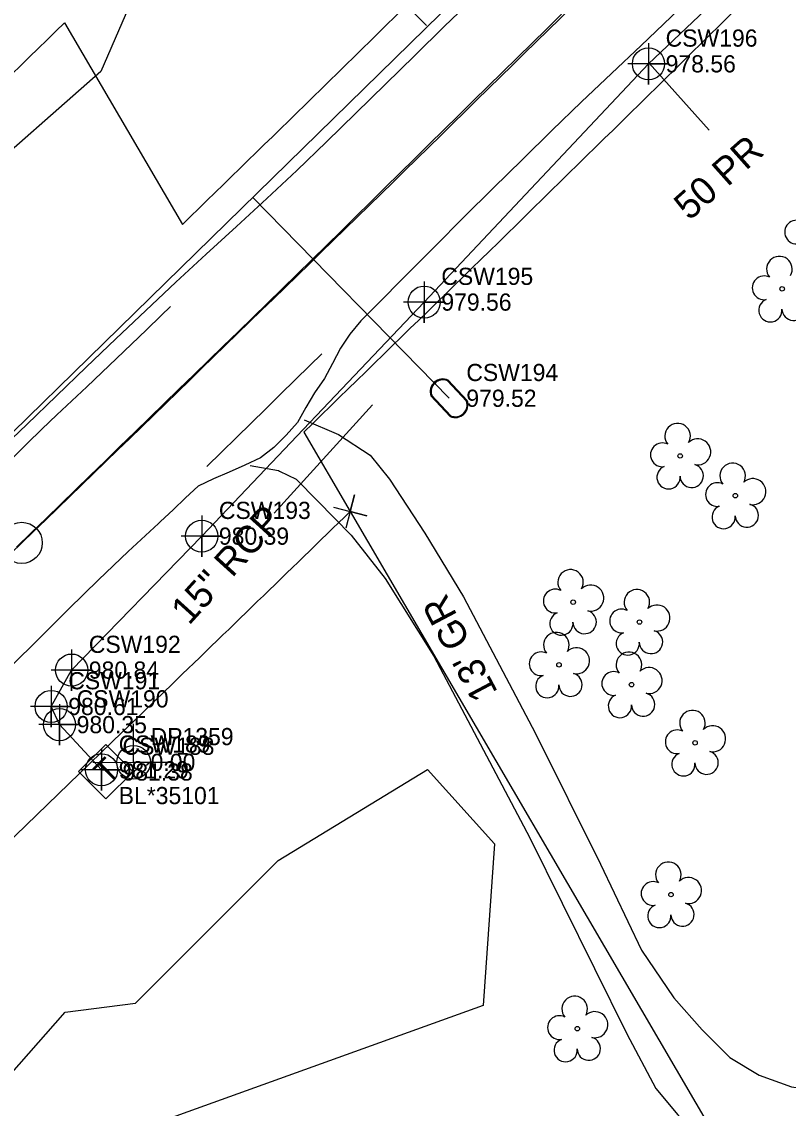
# Model space of a CAD drawing. Extents: x 1182322 to 1186765, y 572295 to 575411.
# Drawn here: x 1185163.2 to 1185274.8, y 574684.8 to 574843 of the extents above; entities that cross this region are included whole.
import ezdxf

# ---------------------------------------------------------------- set-up
doc = ezdxf.new("R2010")
doc.units = 0
for name, color, linetype in [('COGO Default Chain', 7, 'Continuous'), ('Exist Horizontal Alignment', 7, 'Continuous'), ('Exist Horizontal Alignment Point', 7, 'Continuous'), ('Exist Property Corner CELL', 7, 'Continuous'), ('Exist Property Line', 7, 'Continuous'), ('Exist Right of Way Line', 7, 'Continuous'), ('Exist Roads EOP', 7, 'Continuous'), ('Exist Roads EOT', 7, 'Continuous'), ('Exist Roads Soil', 7, 'Continuous'), ('Exist Roads Soil Text', 7, 'Continuous'), ('Exist Structure Minor Pipes RCP 15 Inch', 7, 'Continuous'), ('Exist Structure Minor Pipes RCP 15 Inch Text', 7, 'Continuous'), ('Exist Utilities Power Joint Use Telephone CELL', 7, 'Continuous'), ('Exist Utilities Power Joint Use Telephone Cogo Elevation', 7, 'Continuous'), ('Exist Utilities Power Joint Use Telephone Cogo Number', 7, 'Continuous'), ('Exist Utilities Telephone Pedestal CELL', 7, 'Continuous'), ('Exist Utilities Telephone Pedestal Cogo Elevation', 7, 'Continuous'), ('Exist Utilities Telephone Pedestal Cogo Number', 7, 'Continuous'), ('Exist Utilities Telephone UG Cable SUE LOS C', 7, 'Continuous'), ('Exist Utilities Telephone UG Cable SUE LOS C Cogo Comment', 7, 'Continuous'), ('Exist Utilities Telephone UG Cable SUE LOS C Cogo Elevation', 7, 'Continuous'), ('Exist Utilities Telephone UG Cable SUE LOS C Cogo Number', 7, 'Continuous'), ('Exist Utilities Telephone UG Cable SUE LOS C Cogo Point CELL', 7, 'Continuous'), ('Exist Utilities Telephone UG Cable SUE LOS C Leader', 7, 'Continuous'), ('Exist Utilities Telephone UG Cable SUE LOS C Text', 7, 'Continuous'), ('Exist Utilities Water Meter CELL', 7, 'Continuous'), ('Exist Utilities Water Meter Cogo Elevation', 7, 'Continuous'), ('Exist Utilities Water Meter Cogo Number', 7, 'Continuous'), ('Exist Utilities Water UG Line SUE LOS C', 7, 'Continuous'), ('Exist Vegetation Tree CELL', 7, 'Continuous'), ('Exist Vegetation Woods Line', 7, 'Continuous')]:
    doc.layers.add(name, color=color, linetype=linetype)

msp = doc.modelspace()

# ---------------------------------------------------------------- linework, layer by layer
at = {"layer": 'COGO Default Chain'}
msp.add_arc((1175733.04, 584524.62), 13569.69, 314.022628, 314.679808, dxfattribs=at)
at = {"layer": 'Exist Horizontal Alignment'}
for centre, radius, start, end in [((1175733.04, 584524.62), 13569.69, 314.022628, 314.679808), ((1211496.85, 547519.36), 37893.3, 134.022628, 134.231777)]:
    msp.add_arc(centre, radius, start, end, dxfattribs=at)
at = {"layer": 'Exist Horizontal Alignment Point'}
msp.add_circle((1185163.19, 574767.13), 3, dxfattribs=at)
at = {"layer": 'Exist Property Corner CELL'}
msp.add_line((1185211.02, 574771.7), (1185211.02, 574771.7), dxfattribs=at)
msp.add_lwpolyline([(1185208.6, 574772.34), (1185213.44, 574771.07), (1185211.02, 574771.7), (1185211.66, 574774.12), (1185210.39, 574769.29)], dxfattribs=at)
at = {"layer": 'Exist Property Line'}
msp.add_line((1185211.02, 574771.7), (1185330.03, 574568.05), dxfattribs=at)
at = {"layer": 'Exist Right of Way Line'}
for p, q in [((1185169.44, 574842.87), (1185186.59, 574813.51)), ((1185204.26, 574783.27), (1185211.02, 574771.7))]:
    msp.add_line(p, q, dxfattribs=at)
for centre, radius, start, end in [((1175733.04, 584524.62), 13552.69, 314.230039, 314.679808), ((1175733.04, 584524.62), 13586.69, 314.194478, 314.679808), ((1175733.04, 584524.62), 13519.69, 314.022628, 314.264731), ((1175733.04, 584524.62), 13599.69, 314.022628, 314.18093), ((1211496.85, 547519.36), 37863.3, 134.022628, 134.231777)]:
    msp.add_arc(centre, radius, start, end, dxfattribs=at)
at = {"layer": 'Exist Roads EOP'}
for points in [[(1185279.2, 574864.7), (1185274.93, 574860.49), (1185270.66, 574856.28), (1185266.37, 574852.09), (1185262.07, 574847.9), (1185257.74, 574843.74), (1185253.37, 574839.57), (1185249.07, 574835.46), (1185244.71, 574831.33), (1185240.4, 574827.17), (1185236.11, 574822.97), (1185231.83, 574818.77), (1185227.59, 574814.53), (1185223.35, 574810.28), (1185223.17, 574810.11)], [(1185159.58, 574780.24), (1185163.94, 574784.36), (1185168.25, 574788.54), (1185172.56, 574792.71), (1185176.91, 574796.84), (1185181.28, 574800.95), (1185185.64, 574805.07), (1185190.03, 574809.16), (1185194.46, 574813.2), (1185198.88, 574817.26), (1185203.26, 574821.35), (1185207.59, 574825.51), (1185211.86, 574829.72), (1185216.15, 574833.91), (1185220.43, 574838.11), (1185224.72, 574842.31), (1185229, 574846.51)], [(1185223.16, 574810.1), (1185221.39, 574808.33), (1185219.63, 574806.56), (1185217.86, 574804.79), (1185216.1, 574803.01), (1185214.34, 574801.24), (1185212.59, 574799.46), (1185210.98, 574797.54), (1185209.6, 574795.46), (1185208.44, 574793.24), (1185207.26, 574791.04), (1185205.82, 574789), (1185204.58, 574786.83), (1185203.36, 574784.65), (1185201.69, 574782.79), (1185199.92, 574781.02), (1185197.94, 574779.51), (1185195.67, 574778.46), (1185193.41, 574777.41), (1185191.1, 574776.47), (1185188.86, 574775.38), (1185187.04, 574773.67), (1185185.22, 574771.96), (1185183.39, 574770.25), (1185183.1, 574769.97)], [(1185183.09, 574769.97), (1185178.71, 574765.86), (1185174.37, 574761.73), (1185170.07, 574757.54), (1185165.82, 574753.31), (1185161.56, 574749.08), (1185157.3, 574744.86), (1185153.04, 574740.64), (1185148.78, 574736.42), (1185144.49, 574732.22), (1185140.14, 574728.09), (1185135.79, 574723.96), (1185131.52, 574719.75), (1185127.31, 574715.47), (1185123.09, 574711.21), (1185118.73, 574707.09), (1185114.39, 574702.94), (1185110.1, 574698.74), (1185105.81, 574694.56), (1185101.51, 574690.37), (1185097.22, 574686.18), (1185092.92, 574682)]]:
    msp.add_lwpolyline(points, dxfattribs=at)
at = {"layer": 'Exist Roads EOT'}
for points in [[(1185241.78, 574844.09), (1185239.64, 574841.99), (1185237.5, 574839.89), (1185235.36, 574837.78), (1185233.22, 574835.68), (1185231.08, 574833.58), (1185228.94, 574831.47), (1185226.81, 574829.37), (1185224.67, 574827.26), (1185222.53, 574825.16), (1185220.39, 574823.06), (1185218.26, 574820.95), (1185216.12, 574818.85), (1185213.98, 574816.74), (1185211.85, 574814.64), (1185209.71, 574812.53), (1185207.57, 574810.43), (1185205.43, 574808.33), (1185203.28, 574806.24), (1185201.13, 574804.14), (1185198.98, 574802.05), (1185196.84, 574799.96), (1185194.69, 574797.87), (1185192.54, 574795.77), (1185190.39, 574793.68), (1185188.24, 574791.59), (1185186.09, 574789.5), (1185183.94, 574787.41), (1185181.79, 574785.32), (1185179.64, 574783.23), (1185177.48, 574781.14), (1185175.33, 574779.05), (1185173.18, 574776.96), (1185171.03, 574774.87), (1185168.88, 574772.78), (1185166.73, 574770.69), (1185164.58, 574768.59), (1185162.43, 574766.5)], [(1185161.83, 574779.48), (1185163.97, 574781.58), (1185166.11, 574783.68), (1185168.29, 574785.75), (1185170.47, 574787.8), (1185172.66, 574789.86), (1185174.84, 574791.92), (1185177.01, 574793.99), (1185179.17, 574796.06), (1185181.34, 574798.14), (1185183.48, 574800.24), (1185184.83, 574801.56)], [(1185190.16, 574778.26), (1185192.3, 574780.36), (1185194.44, 574782.46), (1185196.58, 574784.56), (1185198.72, 574786.67), (1185200.86, 574788.77), (1185203, 574790.87), (1185205.15, 574792.96), (1185206.88, 574794.64)]]:
    msp.add_lwpolyline(points, dxfattribs=at)
at = {"layer": 'Exist Roads Soil'}
for points in [[(1185204.3, 574785.05), (1185209.31, 574782.91), (1185213.93, 574779.91), (1185216.72, 574776.43), (1185221.87, 574768.53), (1185227.5, 574759.27), (1185238.01, 574739.38), (1185247.45, 574720.37), (1185253.42, 574707.82), (1185258.15, 574700.91), (1185262.25, 574696.25), (1185266.32, 574692.19)], [(1185196.45, 574778.4), (1185200.57, 574777.69), (1185200.72, 574777.58), (1185203.14, 574776.4), (1185203.14, 574776.4), (1185206.28, 574773.23), (1185206.28, 574773.23), (1185211.16, 574768.24), (1185211.16, 574768.24), (1185216.11, 574761.96), (1185216.11, 574761.96), (1185223.19, 574750.64), (1185237.19, 574724.16), (1185251.32, 574695.67), (1185255.5, 574687.68)], [(1185266.32, 574692.19), (1185270.59, 574689.62), (1185275.28, 574687.95), (1185280.22, 574687.22), (1185285.21, 574687.48), (1185290.06, 574688.71)], [(1185255.5, 574687.68), (1185258.71, 574683.86), (1185262.44, 574680.55), (1185266.62, 574677.81), (1185271.15, 574675.71), (1185275.93, 574674.3), (1185280.88, 574673.59), (1185285.87, 574673.61), (1185290.81, 574674.36), (1185295.59, 574675.81)]]:
    msp.add_lwpolyline(points, dxfattribs=at)
at = {"layer": 'Exist Structure Minor Pipes RCP 15 Inch'}
msp.add_line((1185199.94, 574771.48), (1185214.25, 574787.25), dxfattribs=at)
at = {"layer": 'Exist Utilities Power Joint Use Telephone CELL'}
msp.add_line((1185179.46, 574735.18), (1185179.46, 574735.18), dxfattribs=at)
msp.add_lwpolyline([(1185173.53, 574735.18), (1185184.86, 574735.14), (1185179.46, 574735.16), (1185179.46, 574740.8)], dxfattribs=at)
msp.add_circle((1185179.47, 574735.19), 2.45, dxfattribs=at)
at = {"layer": 'Exist Utilities Telephone Pedestal CELL'}
msp.add_line((1185175.37, 574733.77), (1185175.37, 574733.77), dxfattribs=at)
msp.add_lwpolyline([(1185175.42, 574729.85), (1185179.4, 574733.78), (1185175.46, 574737.76), (1185171.48, 574733.83), (1185175.42, 574729.85)], dxfattribs=at)
at = {"layer": 'Exist Utilities Telephone UG Cable SUE LOS C'}
msp.add_lwpolyline([(1185174.81, 574734.09), (1185168.69, 574740.67), (1185167.47, 574743.31), (1185170.46, 574748.61), (1185189.4, 574768.11), (1185221.79, 574802.19), (1185254.45, 574836.88), (1185289.46, 574870.1), (1185304.2, 574883.75), (1185314.39, 574870.91)], dxfattribs=at)
at = {"layer": 'Exist Utilities Telephone UG Cable SUE LOS C Cogo Point CELL'}
for points in [[(1185254.45, 574839.88), (1185254.45, 574833.88), (1185254.45, 574836.88), (1185257.45, 574836.88), (1185251.45, 574836.88)], [(1185221.79, 574805.19), (1185221.79, 574799.19), (1185221.79, 574802.19), (1185224.79, 574802.19), (1185218.79, 574802.19)], [(1185189.4, 574771.11), (1185189.4, 574765.11), (1185189.4, 574768.11), (1185192.4, 574768.11), (1185186.4, 574768.11)], [(1185170.46, 574751.61), (1185170.46, 574745.61), (1185170.46, 574748.61), (1185173.46, 574748.61), (1185167.46, 574748.61)], [(1185167.47, 574746.31), (1185167.47, 574740.31), (1185167.47, 574743.31), (1185170.47, 574743.31), (1185164.47, 574743.31)], [(1185168.69, 574743.67), (1185168.69, 574737.67), (1185168.69, 574740.67), (1185171.69, 574740.67), (1185165.69, 574740.67)], [(1185174.81, 574737.09), (1185174.81, 574731.09), (1185174.81, 574734.09), (1185177.81, 574734.09), (1185171.81, 574734.09)]]:
    msp.add_lwpolyline(points, dxfattribs=at)
for centre in [(1185254.45, 574836.88), (1185221.79, 574802.19), (1185189.4, 574768.11), (1185170.46, 574748.61), (1185167.47, 574743.31), (1185168.69, 574740.67), (1185174.81, 574734.09)]:
    msp.add_circle(centre, 2.34, dxfattribs=at)
at = {"layer": 'Exist Utilities Telephone UG Cable SUE LOS C Leader'}
msp.add_line((1185254.57, 574837), (1185263.29, 574827.21), dxfattribs=at)
at = {"layer": 'Exist Utilities Water Meter CELL'}
msp.add_line((1185225.43, 574788.19), (1185225.43, 574788.19), dxfattribs=at)
for points in [[(1185225.18, 574790.74), (1185227.96, 574787.77)], [(1185225.28, 574790.84), (1185228.06, 574787.86)], [(1185225.58, 574785.54), (1185222.78, 574788.53)], [(1185225.68, 574785.63), (1185222.88, 574788.62)]]:
    msp.add_lwpolyline(points, dxfattribs=at)
for centre, radius, start, end in [((1185224.53, 574789.14), 1.86, 66.2972, 199.0985), ((1185224.54, 574789.13), 1.73, 68.42, 196.9015), ((1185226.31, 574787.24), 1.86, 246.7674, 19.4275), ((1185226.32, 574787.23), 1.73, 248.2463, 17.9919)]:
    msp.add_arc(centre, radius, start, end, dxfattribs=at)
at = {"layer": 'Exist Utilities Water UG Line SUE LOS C'}
for p, q in [((1185211.15, 574853.66), (1185222.12, 574842.47)), ((1185225.43, 574788.19), (1185196.82, 574817.43))]:
    msp.add_line(p, q, dxfattribs=at)
msp.add_lwpolyline([(1184698.37, 574456.58), (1184835.97, 574463.78), (1185103.91, 574726.55), (1185431.28, 575046.78)], dxfattribs=at)
at = {"layer": 'Exist Vegetation Tree CELL'}
for p, q in [((1185273.91, 574804.11), (1185273.91, 574804.11)), ((1185259.07, 574779.79), (1185259.07, 574779.79)), ((1185267.1, 574774.01), (1185267.1, 574774.01)), ((1185243.49, 574758.5), (1185243.49, 574758.5)), ((1185253.14, 574755.6), (1185253.14, 574755.6)), ((1185241.42, 574749.38), (1185241.42, 574749.38)), ((1185251.99, 574746.49), (1185251.99, 574746.49)), ((1185261.24, 574738.02), (1185261.24, 574738.02)), ((1185257.73, 574715.92), (1185257.73, 574715.92)), ((1185244.09, 574696.39), (1185244.09, 574696.39))]:
    msp.add_line(p, q, dxfattribs=at)
for centre in [(1185273.91, 574804.11), (1185259.07, 574779.79), (1185267.1, 574774.01), (1185243.49, 574758.5), (1185253.14, 574755.6), (1185241.42, 574749.38), (1185251.99, 574746.49), (1185261.24, 574738.02), (1185257.73, 574715.92), (1185244.09, 574696.39)]:
    msp.add_circle(centre, 0.326, dxfattribs=at)
for centre, radius, start, end in [((1185276.02, 574812.38), 1.73, 62.6636, 279.3457), ((1185273.52, 574806.99), 1.86, 330.1651, 219.7134), ((1185271.3, 574804.27), 1.73, 62.6636, 279.3457), ((1185275.58, 574801.21), 1.7, 181.2822, 74.56), ((1185272.2, 574800.99), 1.69, 111.5671, 6.231), ((1185258.69, 574782.67), 1.86, 330.1651, 219.7134), ((1185261.62, 574780.38), 1.9, 257.1011, 134.1999), ((1185256.47, 574779.95), 1.73, 62.6636, 279.3457), ((1185257.37, 574776.67), 1.69, 111.5671, 6.231), ((1185260.75, 574776.89), 1.7, 181.2822, 74.56), ((1185266.71, 574776.88), 1.86, 330.1651, 219.7134), ((1185264.49, 574774.16), 1.73, 62.6636, 279.3457), ((1185269.65, 574774.59), 1.9, 257.1011, 134.1999), ((1185268.77, 574771.11), 1.7, 181.2822, 74.56), ((1185265.39, 574770.88), 1.69, 111.5671, 6.231), ((1185243.1, 574761.38), 1.86, 330.1651, 219.7134), ((1185240.88, 574758.66), 1.73, 62.6636, 279.3457), ((1185246.04, 574759.09), 1.9, 257.1011, 134.1999), ((1185252.76, 574758.48), 1.86, 330.1651, 219.7134), ((1185241.78, 574755.38), 1.69, 111.5671, 6.231), ((1185245.16, 574755.6), 1.7, 181.2822, 74.56), ((1185250.54, 574755.76), 1.73, 62.6636, 279.3457), ((1185255.69, 574756.19), 1.9, 257.1011, 134.1999), ((1185241.04, 574752.25), 1.86, 330.1651, 219.7134), ((1185251.44, 574752.48), 1.69, 111.5671, 6.231), ((1185254.82, 574752.7), 1.7, 181.2822, 74.56), ((1185238.82, 574749.53), 1.73, 62.6636, 279.3457), ((1185243.97, 574749.96), 1.9, 257.1011, 134.1999), ((1185251.61, 574749.37), 1.86, 330.1651, 219.7134), ((1185254.54, 574747.08), 1.9, 257.1011, 134.1999), ((1185239.72, 574746.26), 1.69, 111.5671, 6.231), ((1185243.09, 574746.48), 1.7, 181.2822, 74.56), ((1185249.39, 574746.65), 1.73, 62.6636, 279.3457), ((1185250.29, 574743.37), 1.69, 111.5671, 6.231), ((1185253.67, 574743.59), 1.7, 181.2822, 74.56), ((1185260.86, 574740.89), 1.86, 330.1651, 219.7134), ((1185258.64, 574738.17), 1.73, 62.6636, 279.3457), ((1185263.79, 574738.6), 1.9, 257.1011, 134.1999), ((1185259.54, 574734.89), 1.69, 111.5671, 6.231), ((1185262.91, 574735.12), 1.7, 181.2822, 74.56), ((1185257.34, 574718.8), 1.86, 330.1651, 219.7134), ((1185255.12, 574716.08), 1.73, 62.6636, 279.3457), ((1185260.28, 574716.51), 1.9, 257.1011, 134.1999), ((1185256.03, 574712.8), 1.69, 111.5671, 6.231), ((1185259.4, 574713.02), 1.7, 181.2822, 74.56), ((1185243.71, 574699.27), 1.86, 330.1651, 219.7134), ((1185246.64, 574696.98), 1.9, 257.1011, 134.1999), ((1185241.49, 574696.55), 1.73, 62.6636, 279.3457), ((1185242.39, 574693.27), 1.69, 111.5671, 6.231), ((1185245.76, 574693.49), 1.7, 181.2822, 74.56)]:
    msp.add_arc(centre, radius, start, end, dxfattribs=at)
at = {"layer": 'Exist Vegetation Woods Line'}
for points in [[(1185089.66, 574993.94), (1185105.16, 574955.52), (1185116.98, 574927.11), (1185141.19, 574900.83), (1185141.32, 574883.78), (1185149, 574875.31), (1185180.69, 574860.35), (1185180.82, 574849.87), (1185174.7, 574835.75), (1185136.32, 574801.97)], [(1185169.52, 574698.78), (1185179.75, 574700.09), (1185200.52, 574720.87), (1185222.27, 574734.14), (1185232.01, 574723.32), (1185230.36, 574699.75), (1185172.29, 574678.87), (1185164.16, 574680.82), (1185158.56, 574683.47), (1185157.49, 574685.14), (1185169.52, 574698.78)]]:
    msp.add_lwpolyline(points, dxfattribs=at)

# ---------------------------------------------------------------- texts
at = {"layer": 'Exist Roads Soil Text'}
msp.add_text("13' GR", height=4, rotation=117.8368, dxfattribs=at).set_placement((1185232.57, 574745.4))
at = {"layer": 'Exist Structure Minor Pipes RCP 15 Inch Text'}
msp.add_text('15" RCP', height=4, rotation=47.7712, dxfattribs=at).set_placement((1185187.55, 574755.03))
at = {"layer": 'Exist Utilities Power Joint Use Telephone Cogo Elevation'}
msp.add_text('0.00', height=2.5, dxfattribs=at).set_placement((1185181.96, 574733.93))
at = {"layer": 'Exist Utilities Power Joint Use Telephone Cogo Number'}
msp.add_text('DP1359', height=2.5, dxfattribs=at).set_placement((1185181.96, 574737.68))
at = {"layer": 'Exist Utilities Telephone Pedestal CELL'}
msp.add_text('T', height=3.42, rotation=44.6952, dxfattribs=at).set_placement((1185175.77, 574731.76))
at = {"layer": 'Exist Utilities Telephone Pedestal Cogo Elevation'}
msp.add_text('981.38', height=2.5, dxfattribs=at).set_placement((1185177.87, 574732.52))
at = {"layer": 'Exist Utilities Telephone Pedestal Cogo Number'}
msp.add_text('CSW188', height=2.5, dxfattribs=at).set_placement((1185177.87, 574736.27))
at = {"layer": 'Exist Utilities Telephone UG Cable SUE LOS C Cogo Comment'}
msp.add_text('BL*35101', height=2.5, dxfattribs=at).set_placement((1185177.31, 574729.09))
at = {"layer": 'Exist Utilities Telephone UG Cable SUE LOS C Cogo Elevation'}
for s, p in [('978.56', (1185256.95, 574835.63)), ('979.56', (1185224.29, 574800.94)), ('980.39', (1185191.9, 574766.86)), ('980.84', (1185172.96, 574747.36)), ('980.61', (1185169.97, 574742.06)), ('980.35', (1185171.19, 574739.42)), ('981.29', (1185177.31, 574732.84))]:
    msp.add_text(s, height=2.5, dxfattribs=at).set_placement(p)
at = {"layer": 'Exist Utilities Telephone UG Cable SUE LOS C Cogo Number'}
for s, p in [('CSW196', (1185256.95, 574839.38)), ('CSW195', (1185224.29, 574804.69)), ('CSW193', (1185191.9, 574770.61)), ('CSW192', (1185172.96, 574751.11)), ('CSW191', (1185169.97, 574745.81)), ('CSW190', (1185171.19, 574743.17)), ('CSW189', (1185177.31, 574736.59))]:
    msp.add_text(s, height=2.5, dxfattribs=at).set_placement(p)
at = {"layer": 'Exist Utilities Telephone UG Cable SUE LOS C Text'}
msp.add_text('50 PR', height=4, rotation=41.688, dxfattribs=at).set_placement((1185260.41, 574813.94))
at = {"layer": 'Exist Utilities Water Meter Cogo Elevation'}
msp.add_text('979.52', height=2.5, dxfattribs=at).set_placement((1185227.93, 574786.94))
at = {"layer": 'Exist Utilities Water Meter Cogo Number'}
msp.add_text('CSW194', height=2.5, dxfattribs=at).set_placement((1185227.93, 574790.69))

doc.saveas('drawing.dxf')
